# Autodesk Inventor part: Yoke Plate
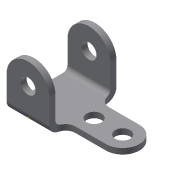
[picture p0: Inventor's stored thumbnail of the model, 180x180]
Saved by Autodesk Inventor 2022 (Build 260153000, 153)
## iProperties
Created: 2011-04
Part Number: Yoke Plate
Material: Generic
Document SubType Name: Modeling
Designer: Dell
Density: 1 g/cm^3
Appearance: Default
Author: Dell
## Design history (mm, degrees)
sketch "Sketch1"
  geometry: 1 further point
sketch "Sketch2"
  geometry: L1 (28.5, 36.5)-(28.5, -7.5); L2 (-28.5, -7.5)-(28.5, -7.5); L3 (-28.5, 36.5)-(-28.5, -7.5); C1 r 10 at (0, 36.5); A1 r 28.5 centre (0, 36.5) between (28.5, 36.5) and (-28.5, 36.5); 2 further points
  constraints: 6 end point, 2 centre point, 2 point on circle, 2 tangent, 2 vertical, 1 coincident, 1 perpendicular, 1 other
  dimensions: "d0" = 57 distance of L2.start L1.end; "d1" = 36.5 distance of point (0, 0) C1.centre; "d2" = 28.5 distance from line of L1 point (0, 0); "d3" = 20 diameter of C1; "d24" = 7.5 distance from line of point (0, 0) L2
extrude "Extrusion1" new body sketch "Sketch2" distance "d4" = 89; taper "d5" = 0 deg
sketch "Sketch3"
  geometry: L1 (44, 89)-(0, 89) reference; L2 (-28.588, 8)-(36.5, 8); L3 (36.5, 8)-(36.5, 81); L4 (36.5, 81)-(-28.588, 81); L5 (-28.588, 8)-(-28.588, 81); L6 (-28.5, 89)-(0, 89) reference; 3 further points
  constraints: 8 end point, 1 perpendicular
  dimensions: "d6" = 73 distance of L2.start L4.end; "d9" = 8 distance between parallel lines of L1 L4
extrude "Extrusion2" cut sketch "Sketch3" distance "d10" = 89; taper "d11" = 0 deg
sketch "Sketch4"
  geometry: L1 (0, 58.08)-(53.5, 58.08); L2 (53.5, 13.58)-(0, 13.58); L3 (0, 13.58)-(0, 58.08); L4 (0, 35.83)-(93.365, 35.83); L5 (0, 73)-(0, 0) reference; C1 r 10 at (53.5, 35.83); C2 r 10 at (15.5, 35.83); A1 r 22.25 centre (53.5, 35.83) between (53.5, 13.58) and (53.5, 58.08); 1 further point
  constraints: 8 end point, 3 centre point, 2 horizontal, 2 point on circle, 1 coincident, 1 collinear, 1 equal radius, 1 horizontal alignment, 1 parallel, 1 perpendicular, 1 point on line, 1 tangent
  dimensions: "d12" = 44.5 diameter of A1; "d13" = 44.5 distance between parallel lines of L2 L1; "d14" = 20 diameter of C1; "d15" = 38 distance of A1.centre C2.centre; "d23" = 15.5 distance from line of C2.centre L3
extrude "Extrusion3" join sketch "Sketch4" stored distance "d16" = 89; taper "d17" = 0 deg
fillet "Fillet1" dims "d18" = 12.7
fillet "Fillet2" dims "d19" = 6.35
fillet "Fillet3" dims "d20" = 12.75
body "Solid1"
